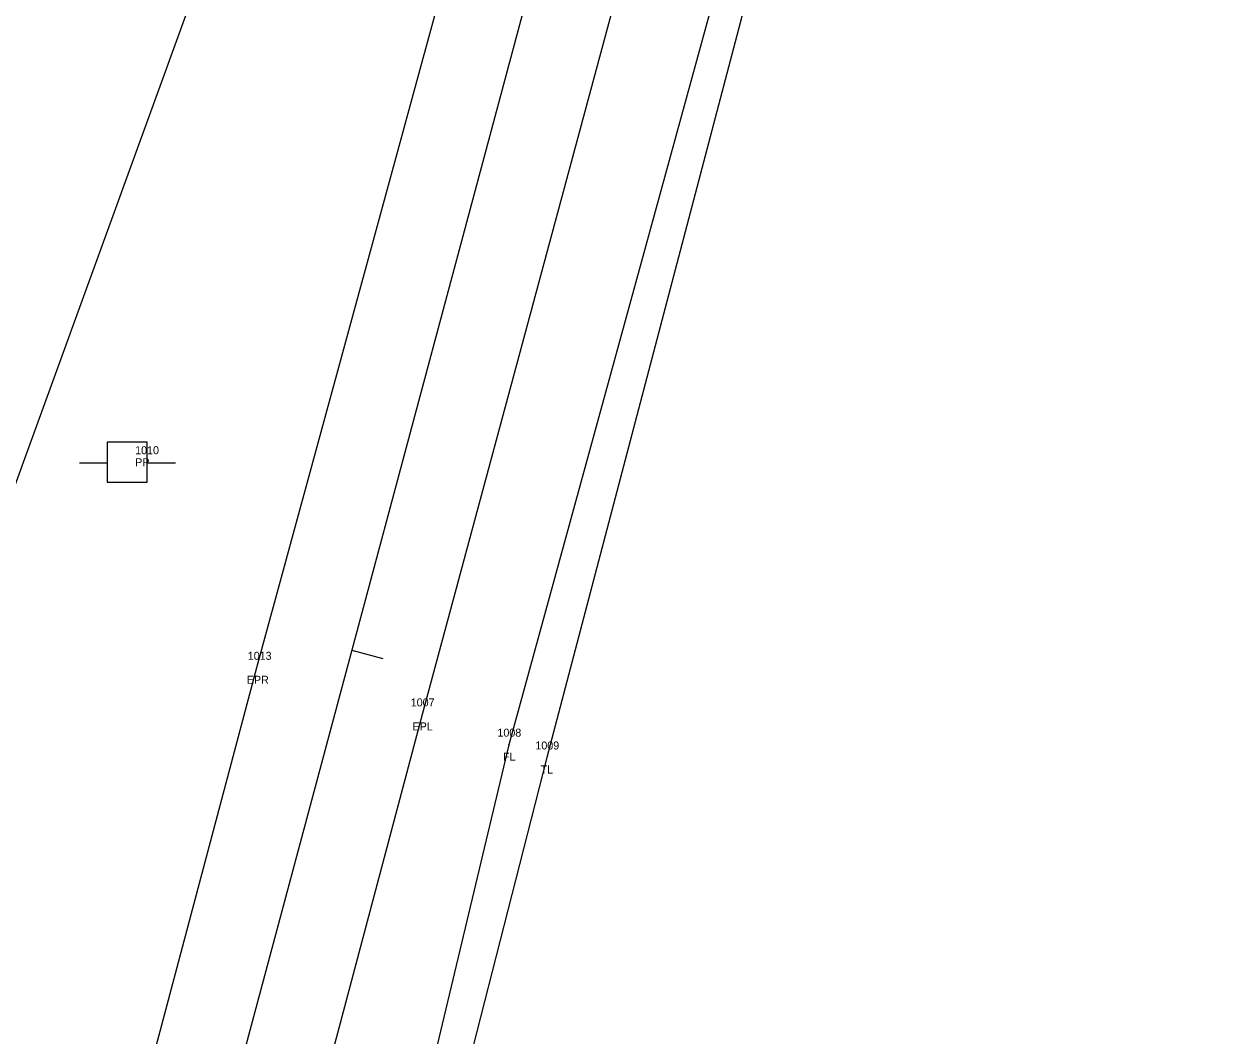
# Model space of a CAD drawing. Extents: x 2432632 to 2433497, y 684847 to 688233.
# Drawn here: x 2433046.6 to 2433197.4, y 687841.9 to 687968.3 of the extents above; entities that cross this region are included whole.
import ezdxf

# ---------------------------------------------------------------- set-up
doc = ezdxf.new("R2010")
doc.units = 0
for name, color, linetype in [('RD_EX_Fence_Other', 7, 'Continuous'), ('RD_EX_Fence_Other_txCode', 7, 'Continuous'), ('RD_EX_Road', 7, 'Continuous'), ('RD_EX_Road_txCode', 7, 'Continuous'), ('RD_EX_UT', 7, 'Continuous'), ('RD_EX_UT_txCode', 7, 'Continuous'), ('RD_EX_VEG', 7, 'Continuous'), ('RD_EX_VEG_txCode', 7, 'Continuous'), ('RD_HC_Cl', 7, 'Continuous'), ('RD_HC_Data_Tic', 7, 'Continuous'), ('RD_SMD_Locator', 7, 'Continuous')]:
    doc.layers.add(name, color=color, linetype=linetype)

msp = doc.modelspace()

# ---------------------------------------------------------------- linework, layer by layer
at = {"layer": 'RD_EX_Fence_Other'}
msp.add_lwpolyline([(2433163.32, 688082.84), (2433107.2, 687878.29), (2433065.65, 687704.2), (2433063.62, 687678.63), (2433060.64, 687652.01)], dxfattribs=at)
at = {"layer": 'RD_EX_Road'}
for points in [[(2433130.63, 688090.22), (2433103.18, 687988.73), (2433075.68, 687887.89), (2433049.83, 687790.75), (2433022.33, 687689.17), (2432994.76, 687586.82), (2432966.23, 687480.17), (2432943.15, 687390.42), (2432931.4, 687334.3), (2432921.83, 687273.88), (2432915.64, 687215.4), (2432913.86, 687159.12), (2432915.08, 687107.55), (2432919.97, 687053.4), (2432928.7, 686998.89), (2432946.77, 686924.59), (2432964.57, 686864), (2432997.3, 686766.34), (2433031.44, 686666.38), (2433066.06, 686565.78), (2433098.73, 686469.74)], [(2433151.11, 688085.43), (2433123.35, 687982.08), (2433096.36, 687882.07), (2433070.62, 687785.25), (2433042.64, 687684.31), (2433015.24, 687582.49), (2432986.34, 687474.01), (2432964, 687384.38)]]:
    msp.add_lwpolyline(points, dxfattribs=at)
at = {"layer": 'RD_EX_UT'}
for p, q in [((2433062, 687916.07), (2433057, 687916.07)), ((2433057, 687916.07), (2433057, 687911.07)), ((2433062, 687911.07), (2433062, 687916.07)), ((2433053.57, 687913.5), (2433057.04, 687913.5)), ((2433061.93, 687913.5), (2433065.57, 687913.5)), ((2433057, 687911.07), (2433062, 687911.07))]:
    msp.add_line(p, q, dxfattribs=at)
at = {"layer": 'RD_EX_VEG'}
for points in [[(2433112.43, 688094.61), (2433041.17, 687898.89), (2432988.9, 687699.78), (2432947.96, 687578.08), (2432935.9, 687556.87), (2432944.3, 687538.7), (2432913.88, 687397.98), (2432902.4, 687330.02), (2432885.78, 687157.56), (2432894.43, 687032.93), (2432918.07, 686924.4), (2432974.73, 686759.54), (2433073.82, 686456.42), (2433099.9, 686365.23), (2433115.47, 686257.21), (2433114.64, 686158.77), (2433095.68, 686092.78)], [(2433166.25, 688082.87), (2433111.93, 687876.69), (2433067.75, 687703.46), (2433065.05, 687678.03), (2433052.74, 687645.62), (2433005.45, 687469.88), (2432979.96, 687326.61), (2432966.8, 687267.34), (2432959.05, 687210.65), (2432959.25, 687071.62), (2432974.82, 687014.37), (2432998.13, 686938.9), (2433012.99, 686878.7), (2433054.45, 686782.35), (2433123.54, 686586.06), (2433129.82, 686546.35), (2433158.34, 686434.26), (2433192.79, 686274.67), (2433189.42, 686162.6), (2433197.4, 686074.41)]]:
    msp.add_lwpolyline(points, dxfattribs=at)
at = {"layer": 'RD_HC_Cl'}
msp.add_line((2433140.58, 688087.72), (2432956.34, 687400.83), dxfattribs=at)
at = {"layer": 'RD_HC_Data_Tic'}
msp.add_line((2433087.57, 687890.1), (2433091.44, 687889.07), dxfattribs=at)
at = {"layer": 'RD_SMD_Locator'}
for centre in [(2433075.68, 687887.89), (2433096.36, 687882.07), (2433107.2, 687878.29), (2433111.93, 687876.69)]:
    msp.add_circle(centre, 0.001, dxfattribs=at)

# ---------------------------------------------------------------- texts
at = {"layer": 'RD_EX_Fence_Other_txCode'}
for s, p in [('1008', (2433105.77, 687879.29)), ('FL', (2433106.47, 687876.29))]:
    msp.add_text(s, height=1, dxfattribs=at).set_placement(p)
at = {"layer": 'RD_EX_Road_txCode'}
for s, p in [('1013', (2433074.58, 687888.89)), ('EPR', (2433074.46, 687885.89)), ('1007', (2433094.94, 687883.07)), ('EPL', (2433095.16, 687880.07))]:
    msp.add_text(s, height=1, dxfattribs=at).set_placement(p)
at = {"layer": 'RD_EX_UT_txCode'}
for s, p in [('1010', (2433060.51, 687914.56)), ('PP', (2433060.51, 687913.06))]:
    msp.add_text(s, height=1, dxfattribs=at).set_placement(p)
at = {"layer": 'RD_EX_VEG_txCode'}
for s, p in [('1009', (2433110.51, 687877.69)), ('TL', (2433111.16, 687874.69))]:
    msp.add_text(s, height=1, dxfattribs=at).set_placement(p)

doc.saveas('drawing.dxf')
